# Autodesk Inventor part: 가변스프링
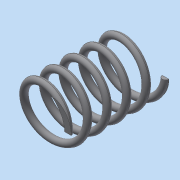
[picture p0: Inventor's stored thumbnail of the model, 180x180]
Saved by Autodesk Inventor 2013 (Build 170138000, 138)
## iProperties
Created: 2018-10
Part Number: 가변스프링
Material: 일반
Document SubType Name: Modeling
Designer: Administrator
Density: 1 g/cm^3
Author: Administrator
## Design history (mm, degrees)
sketch "스케치1"
  geometry: L1 (0, 0)-(0, 29.235); L2 (0, 0)-(8, 0); L3 (0, 29.235)-(8, 29.235); C1 r 1 at (8, 0)
  constraints: 6 end point, 1 centre point, 1 horizontal alignment, 1 parallel, 1 perpendicular, 1 vertical
  dimensions: "d0" = 29.23502 distance of L1.start L1.end (derived); "d1" = 2 diameter of C1; "d2" = 16 diameter of L2.end L1; "d3" = 8 distance of L1.end L3.end
feature "코일1" sketch "스케치1" pitch "d4" = 10; turns "d6" = 5; dims "d5" = 29.23502 (= d0), "d7" = 0, angle "d8" = 90 deg, angle "d9" = 90 deg, "d10" = 0, "d11" = 0
sketch "스케치2"
  geometry: L1 (29.235, 10)-(0, 10); L2 (0, 10)-(0, -10); L3 (0, -10)-(29.235, -10); L4 (29.235, -10)-(29.235, 10); 2 further points
  constraints: 8 end point, 2 parallel, 1 coincident, 1 horizontal, 1 midpoint, 1 perpendicular
  dimensions: "d12" = 20 distance of L1.end L2.end; "d14" = 29.23502 distance of L2.end L3.end (derived)
extrude "돌출1" sketch "스케치2" stored distance "d15" = 0; taper "d16" = 0 deg
node "솔리드1"
